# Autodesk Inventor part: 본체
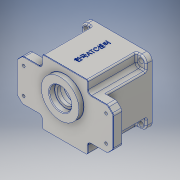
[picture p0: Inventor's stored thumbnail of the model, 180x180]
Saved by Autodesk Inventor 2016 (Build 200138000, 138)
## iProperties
Created: 2017-01
Part Number: 본체
Material: 알루미늄 6061
Document SubType Name: Modeling
Designer: Owner
Mass: 1020.14 g
Surface Area: 841.177 cm^2
Volume: 377.828 cm^3
Density: 2.7 g/cm^3
Appearance: 알루미늄 - 평지
Author: Owner
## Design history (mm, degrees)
sketch "스케치1"
  geometry: L1 (-47, -47)-(47, -47); L2 (47, -47)-(47, 47); L3 (47, 47)-(-47, 47); L4 (-47, 47)-(-47, -47); L5 (-47, -47)-(47, 47); L6 (47, -47)-(-47, 47); 1 further point
  constraints: 12 end point, 2 midpoint, 2 parallel, 1 horizontal, 1 perpendicular
  dimensions: "d0" = 94 distance of L3.end L2.end; "d1" = 94 distance of L2.end L1.end
extrude "돌출1" new body sketch "스케치1" distance "d2" = 9; taper "d3" = 0 deg
sketch "스케치4"
  geometry: L1 (-47, 47)-(47, 47) reference; L2 (-33, 47)-(33, 47); L3 (33, 30)-(47, 30); L4 (47, 30)-(47, -30); L5 (47, -30)-(33, -30); L6 (33, -30)-(33, -47); L7 (47, -47)-(-47, -47) reference; L8 (33, -47)-(-33, -47); L9 (-33, -30)-(-33, -47); L10 (-33, -30)-(-47, -30); L11 (-47, -30)-(-47, 30); L12 (-47, 30)-(-33, 30); L13 (-33, 30)-(-33, 47); L14 (33, 47)-(33, 30); L15 (47, -47)-(47, 47) reference; L16 (-47, 47)-(-47, -47) reference; 5 further points
  constraints: 24 end point, 7 perpendicular, 5 midpoint, 5 point on line, 2 horizontal, 2 vertical alignment, 1 collinear, 1 horizontal alignment, 1 vertical
  dimensions: "d10" = 66 distance of L2.end L2.start; "d11" = 66 distance of L6.end L8.end; "d12" = 60 distance of L10.end L11.end; "d13" = 60 distance of L3.end L4.end
extrude "돌출4" join sketch "스케치4" distance "d16" = 71; taper "d17" = 0 deg
sketch "스케치6"
  geometry: C1 r 43 at (0, 0); 1 further point
  constraints: 1 centre point, 1 coincident
  dimensions: "d18" = 86 diameter of C1
extrude "돌출5" cut sketch "스케치6" distance "d19" = 9; taper "d20" = 0 deg
sketch "스케치7"
  geometry: C1 r 40 at (0, 0); 1 further point
  constraints: 1 centre point, 1 coincident
  dimensions: "d21" = 80 diameter of C1
extrude "돌출6" cut sketch "스케치7" distance "d22" = 62; taper "d23" = 0 deg
sketch "스케치8"
  geometry: A1 r 4 centre (-36, 0) between (-35.852, -3.997) and (-35.852, 3.997); A2 r 40 centre (0, 0) between (-39.148, 8.214) and (-39.148, -8.214) reference; A3 r 3.5 centre (-35.722, 7.495) between (-39.148, 8.214) and (-35.852, 3.997); A4 r 3.5 centre (-35.722, -7.495) between (-35.852, -3.997) and (-39.148, -8.214); 1 further point
  constraints: 8 point on circle, 4 tangent, 3 centre point, 1 horizontal alignment
  dimensions: "d25" = 8 diameter of A1; "d26" = 36 distance of point (0, 0) A1.centre; "d40" = 7 diameter of A3; "d41" = 7 diameter of A4
sketch "스케치9"
  geometry: L1 (33, 47)-(-33, 47) reference; L2 (-33, -47)-(33, -47) reference; C1 r 27.5 at (0, 11); 1 further point
  constraints: 1 centre point, 1 vertical alignment
  dimensions: "d27" = 55 diameter of C1; "d29" = 58 distance from line of L2 C1.centre
extrude "돌출7" join sketch "스케치9" distance "d30" = 7; taper "d31" = 0 deg
sketch "스케치10"
  geometry: C1 r 27.5 at (0, 0) reference; C2 r 16 at (0, 0); 1 further point
  constraints: 1 centre point, 1 coincident
  dimensions: "d32" = 32 diameter of C2
extrude "돌출8" cut sketch "스케치10" distance "d33" = 8; taper "d34" = 0 deg
sketch "스케치11"
  geometry: C1 r 16 at (0, 0) reference; C2 r 12.5 at (0, 0); 1 further point
  constraints: 1 centre point, 1 coincident
  dimensions: "d35" = 25 diameter of C2
extrude "돌출9" cut sketch "스케치11" distance "d36" = 5; taper "d37" = 0 deg
chamfer "모따기1" distance "d48" = 1; stored, may be unused: second distance "d49" = 2, angle "d50" = 45 deg
sketch "스케치20"
  geometry: L1 (-47, 30)-(-33, 30) reference; L2 (-47, 30)-(-70, 30); L3 (47, -30)-(47, 30) reference; L4 (-47, 30)-(-47, -30) reference; L5 (-70, 30)-(-70, -30); L6 (-33, -30)-(-47, -30) reference; L7 (-70, -30)-(-47, -30); L8 (-47, 30)-(-47, -30); 1 further point
  constraints: 8 end point, 1 collinear, 1 horizontal, 1 vertical
  dimensions: "d70" = 23 distance of L1.start L2.end; "d71" = 60 distance of L2.end L5.end
extrude "돌출15" join sketch "스케치20" distance "d72" = 13; taper "d73" = 0 deg
chamfer "모따기3" distance "d74" = 8; stored, may be unused: second distance "d75" = 2, angle "d76" = 45 deg
sketch "스케치23"
  geometry: L1 (70, -22)-(70, 22) reference; L2 (62, 30)-(47, 30) reference; 2 further points
  dimensions: "d82" = 10 distance from line of point (60, 19) L1; "d83" = 11 distance from line of L2 point (60, 19)
hole "구멍1" sketch "스케치23" at (60, 19) diameter "d84" = 4; stored, may be unused: countersink angle "d88" = 90 deg, drill point angle "d90" = 118 deg; dims "d85" = 6, "d86" = 10, "d87" = 4, "d89" = 8
fillet "모깎기7" dims "d92" = 5
fillet "모깎기8" dims "d93" = 8
chamfer "모따기4" distance "d115" = 1; stored, may be unused: second distance "d116" = 2, angle "d117" = 45 deg
sketch "스케치24"
  geometry: L1 (-6, 80)-(72, 80) reference; 2 further points
  constraints: 1 vertical alignment, 1 other
  dimensions: "d118" = 40 distance from line of L1 point (33, 40)
feature "엠보싱1" sketch "스케치24" dims "d10" = 66, "d11" = 66, "d12" = 60, "d13" = 60, "d119" = 0.5, "d120" = 0
fillet "모깎기10" dims "d121" = 5
fillet "모깎기11" dims "d122" = 2
fillet "모깎기12" dims "d123" = 2
fillet "모깎기13" dims "d124" = 2
fillet "모깎기14" dims "d125" = 2
fillet "모깎기15" dims "d126" = 2
fillet "모깎기16" dims "d127" = 2
sketch "스케치25"
  geometry: 2 further points
  dimensions: "d128" = 40 horizontal distance of point (0, 0) point (-40, 40); "d129" = 40 horizontal distance of point (0, 0) point (-40, 40)
hole "구멍4" sketch "스케치25" at (-40, 40) diameter "d130" = 7; stored, may be unused: countersink angle "d134" = 90 deg, drill point angle "d136" = 118 deg; dims "d131" = 6, "d132" = 4, "d133" = 2, "d135" = 8
fillet "모깎기17" dims "d137" = 0.3
fillet "모깎기18" dims "d140" = 0.3
sketch "스케치31"
  geometry: 1 further point
sketch "스케치32"
  geometry: 1 further point
extrude "돌출20" join sketch "스케치8" stored distance "d154" = 5; taper "d155" = 0 deg
hole "구멍6" diameter "d158" = 3.242; stored, may be unused: countersink angle "d162" = 90 deg, drill point angle "d164" = 118 deg; dims "d156" = 10, "d157" = 10, "d159" = 7, "d160" = 4, "d161" = 2, "d163" = 9
sketch "스케치33"
  geometry: C1 r 21 at (0, 11); 2 further points
  constraints: 1 centre point, 1 coincident
  dimensions: "d165" = 42 diameter of C1
extrude "돌출21" join sketch "스케치33" distance "d166" = 7; taper "d167" = 0 deg
sketch "스케치34"
  geometry: C1 r 17.5 at (0, 0); C2 r 21 at (0, 0) reference; 1 further point
  constraints: 1 centre point, 1 concentric
  dimensions: "d168" = 35 diameter of C1
extrude "돌출22" cut sketch "스케치34" distance "d169" = 10; taper "d170" = 0 deg
sketch "스케치35"
  geometry: A1 r 15 centre (0, -20) between (-8.978, -7.984) and (8.978, -7.984); A2 r 21 centre (0, 11) between (8.978, -7.984) and (-8.978, -7.984) reference; 1 further point
  constraints: 4 point on circle, 1 centre point, 1 vertical alignment
  dimensions: "d171" = 20 distance of A1.centre point (0, 0); "d172" = 30 diameter of A1
extrude "돌출23" join sketch "스케치35" distance "d173" = 7; taper "d174" = 0 deg
sketch "스케치36"
  geometry: C1 r 11 at (0, -20); A1 r 15 centre (0, -20) between (-8.978, -7.984) and (8.978, -7.984) reference; 1 further point
  constraints: 1 centre point, 1 concentric
  dimensions: "d175" = 22 diameter of C1
extrude "돌출24" cut sketch "스케치36" distance "d176" = 7; taper "d177" = 0 deg
sketch "스케치37"
  geometry: C1 r 11 at (0, 0) reference; C2 r 9.5 at (0, 0); 1 further point
  constraints: 1 centre point, 1 coincident
  dimensions: "d178" = 19 diameter of C2
extrude "돌출25" cut sketch "스케치37" distance "d179" = 1; taper "d180" = 0 deg
fillet "모깎기19" dims "d181" = 3
fillet "모깎기20" dims "d182" = 2
chamfer "모따기5" distance "d183" = 1; stored, may be unused: second distance "d184" = 2, angle "d185" = 45 deg
fillet "모깎기21" dims "d186" = 0.3
fillet "모깎기22" dims "d187" = 0.3
fillet "모깎기23" dims "d188" = 0.3
sketch "스케치39"
  geometry: 1 further point
fillet "모깎기24" dims "d192" = 2
sketch "스케치40"
  geometry: L1 (31, 47)-(-31, 47) reference; L2 (-33, 45)-(-33, 35) reference; L3 (-38, 30)-(-59.929, 30) reference; L4 (-63.464, 28.536)-(-68.536, 23.464) reference; L5 (-70, 19.929)-(-70, -19.929) reference; L6 (-68.536, -23.464)-(-63.464, -28.536) reference; L7 (-59.929, -30)-(-38, -30) reference; L8 (-33, -35)-(-33, -45) reference; L9 (-31, -47)-(31, -47) reference; L10 (33, -45)-(33, -35) reference; L11 (38, -30)-(59.929, -30) reference; L12 (63.464, -28.536)-(68.536, -23.464) reference; L13 (70, -19.929)-(70, 19.929) reference; L14 (33, 35)-(33, 45) reference; L15 (59.929, 30)-(38, 30) reference; L16 (68.536, 23.464)-(63.464, 28.536) reference; L17 (-32.7, 35)-(-32.7, 45) reference; L18 (-59.929, 29.7)-(-38, 29.7) reference; L19 (-68.323, 23.252)-(-63.252, 28.323) reference; L20 (-69.7, -19.929)-(-69.7, 19.929) reference; L21 (-63.252, -28.323)-(-68.323, -23.252) reference; L22 (-38, -29.7)-(-59.929, -29.7) reference; L23 (-32.7, -45)-(-32.7, -35) reference; L24 (31, -46.7)-(-31, -46.7) reference; L25 (32.7, -35)-(32.7, -45) reference; L26 (59.929, -29.7)-(38, -29.7) reference; L27 (68.323, -23.252)-(63.252, -28.323) reference; L28 (69.7, 19.929)-(69.7, -19.929) reference; L29 (63.252, 28.323)-(68.323, 23.252) reference; L30 (38, 29.7)-(59.929, 29.7) reference; L31 (32.7, 45)-(32.7, 35) reference; L32 (-31, 46.7)-(31, 46.7) reference; L33 (-59.929, 29)-(-38, 29); L34 (-32, 35)-(-32, 45); L35 (-31, 46)-(31, 46); L36 (32, 45)-(32, 35); L37 (38, 29)-(59.929, 29); L38 (62.757, 27.828)-(67.828, 22.757); L39 (69, 19.929)-(69, -19.929); L40 (67.828, -22.757)-(62.757, -27.828); L41 (59.929, -29)-(38, -29); L42 (32, -35)-(32, -45); L43 (31, -46)-(-31, -46); L44 (-32, -45)-(-32, -35); L45 (-38, -29)-(-59.929, -29); L46 (-62.757, -27.828)-(-67.828, -22.757); L47 (-69, -19.929)-(-69, 19.929); L48 (-67.828, 22.757)-(-62.757, 27.828); C1 r 2 at (-60, 19) reference; C2 r 2 at (60, 19) reference; C3 r 2 at (-60, -19) reference; C4 r 2 at (60, -19) reference; C5 r 27.8 at (0, 11) reference; A1 r 2 centre (-31, 45) between (-31, 47) and (-33, 45) reference; A2 r 5 centre (-38, 35) between (-38, 30) and (-33, 35) reference; A3 r 5 centre (-59.929, 25) between (-59.929, 30) and (-63.464, 28.536) reference; A4 r 5 centre (-65, 19.929) between (-68.536, 23.464) and (-70, 19.929) reference; A5 r 5 centre (-65, -19.929) between (-70, -19.929) and (-68.536, -23.464) reference; A6 r 5 centre (-59.929, -25) between (-63.464, -28.536) and (-59.929, -30) reference; A7 r 5 centre (-38, -35) between (-33, -35) and (-38, -30) reference; A8 r 2 centre (-31, -45) between (-33, -45) and (-31, -47) reference; A9 r 2 centre (31, -45) between (31, -47) and (33, -45) reference; A10 r 5 centre (38, -35) between (38, -30) and (33, -35) reference; A11 r 5 centre (59.929, -25) between (59.929, -30) and (63.464, -28.536) reference; A12 r 5 centre (65, -19.929) between (68.536, -23.464) and (70, -19.929) reference; A13 r 2 centre (31, 45) between (33, 45) and (31, 47) reference; A14 r 5 centre (38, 35) between (33, 35) and (38, 30) reference; A15 r 5 centre (59.929, 25) between (63.464, 28.536) and (59.929, 30) reference; A16 r 5 centre (65, 19.929) between (70, 19.929) and (68.536, 23.464) reference; A17 r 1.7 centre (-31, 45) between (-31, 46.7) and (-32.7, 45) reference; A18 r 5.3 centre (-38, 35) between (-38, 29.7) and (-32.7, 35) reference; A19 r 4.7 centre (-59.929, 25) between (-59.929, 29.7) and (-63.252, 28.323) reference; A20 r 4.7 centre (-65, 19.929) between (-68.323, 23.252) and (-69.7, 19.929) reference; A21 r 4.7 centre (-65, -19.929) between (-69.7, -19.929) and (-68.323, -23.252) reference; A22 r 4.7 centre (-59.929, -25) between (-63.252, -28.323) and (-59.929, -29.7) reference; A23 r 5.3 centre (-38, -35) between (-32.7, -35) and (-38, -29.7) reference; A24 r 1.7 centre (-31, -45) between (-32.7, -45) and (-31, -46.7) reference; A25 r 1.7 centre (31, -45) between (31, -46.7) and (32.7, -45) reference; A26 r 5.3 centre (38, -35) between (38, -29.7) and (32.7, -35) reference; A27 r 4.7 centre (59.929, -25) between (59.929, -29.7) and (63.252, -28.323) reference; A28 r 4.7 centre (65, -19.929) between (68.323, -23.252) and (69.7, -19.929) reference; A29 r 4.7 centre (65, 19.929) between (69.7, 19.929) and (68.323, 23.252) reference; A30 r 4.7 centre (59.929, 25) between (63.252, 28.323) and (59.929, 29.7) reference; A31 r 5.3 centre (38, 35) between (32.7, 35) and (38, 29.7) reference; A32 r 1.7 centre (31, 45) between (32.7, 45) and (31, 46.7) reference; A33 r 6 centre (-38, 35) between (-38, 29) and (-32, 35); A34 r 1 centre (-31, 45) between (-31, 46) and (-32, 45); A35 r 1 centre (31, 45) between (32, 45) and (31, 46); A36 r 6 centre (38, 35) between (32, 35) and (38, 29); A37 r 4 centre (59.929, 25) between (62.757, 27.828) and (59.929, 29); A38 r 4 centre (65, 19.929) between (69, 19.929) and (67.828, 22.757); A39 r 4 centre (65, -19.929) between (67.828, -22.757) and (69, -19.929); A40 r 4 centre (59.929, -25) between (59.929, -29) and (62.757, -27.828); A41 r 6 centre (38, -35) between (38, -29) and (32, -35); A42 r 1 centre (31, -45) between (31, -46) and (32, -45); A43 r 1 centre (-31, -45) between (-32, -45) and (-31, -46); A44 r 6 centre (-38, -35) between (-32, -35) and (-38, -29); A45 r 4 centre (-59.929, -25) between (-62.757, -27.828) and (-59.929, -29); A46 r 4 centre (-65, -19.929) between (-69, -19.929) and (-67.828, -22.757); A47 r 4 centre (-65, 19.929) between (-67.828, 22.757) and (-69, 19.929); A48 r 4 centre (-59.929, 25) between (-59.929, 29) and (-62.757, 27.828); 1 further point
  constraints: 32 end point, 32 point on circle, 16 centre point, 31 other
  dimensions: "d195" = 1 distance between parallel lines of L3 L33
extrude "돌출27" cut sketch "스케치40" distance "d193" = 1; taper "d194" = 0 deg
fillet "모깎기25" dims "d196" = 2
node "솔리드1"
mirror "대칭2"
mirror "대칭3"
mirror "대칭4"
mirror "대칭8"
mirror "대칭9"
mirror "대칭12"
mirror "대칭13"
node "투영된 루프4"
